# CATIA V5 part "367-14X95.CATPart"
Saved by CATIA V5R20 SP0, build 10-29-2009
Part number: 367-14X95
Definition: NONE
Nomenclature: 367-14X95
Source: Unknown
Description: 367-14X95
Bounding box of the stored display mesh (mm): x 0 to 95, y -14 to 14, z -14 to 14
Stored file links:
  C:\Users\Utente\Desktop\IO LAVORO\3D X SITO CF\X SITO\PLASTICA\3D files 367\367-14X95.CATPart
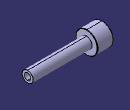
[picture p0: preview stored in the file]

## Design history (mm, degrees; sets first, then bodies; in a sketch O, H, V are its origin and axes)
Body1 "367-14X95" (main body)
  Solid1: solid without history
